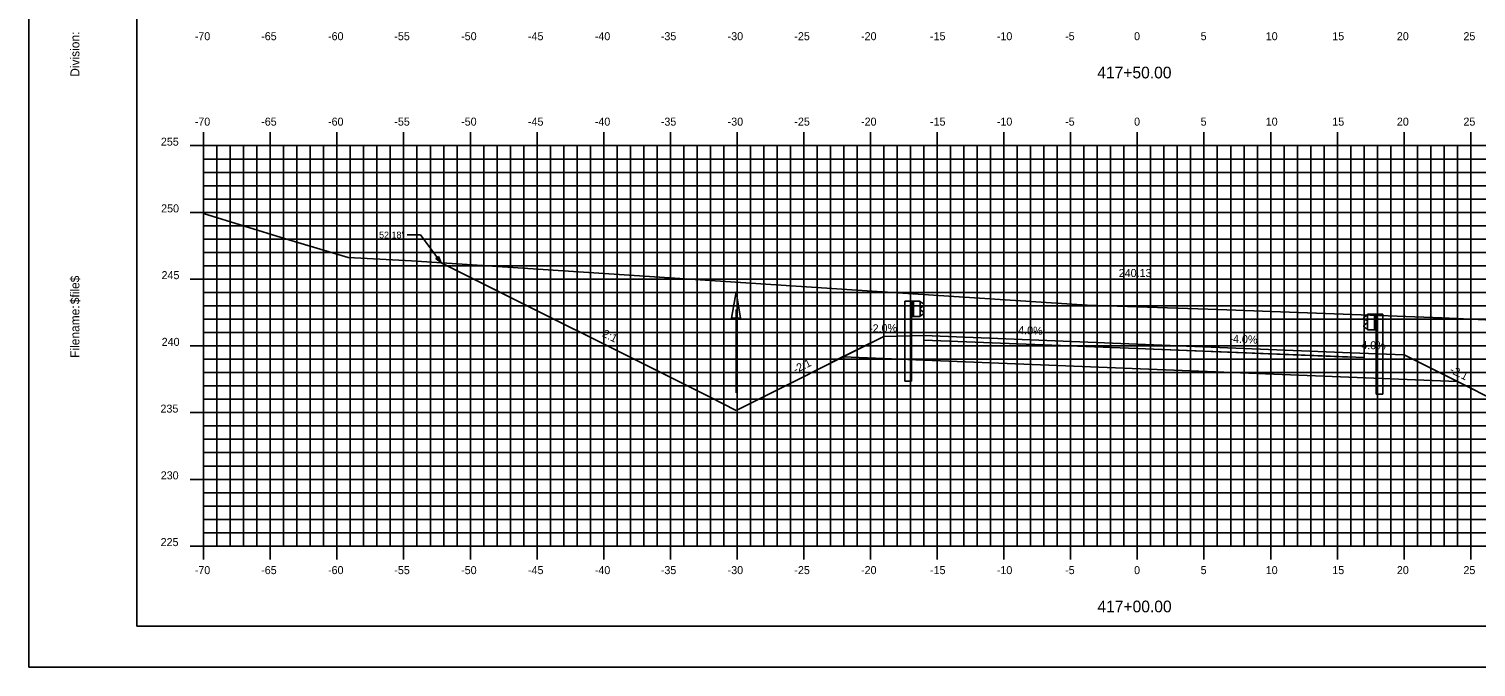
# Model space of a CAD drawing. Extents: x 1160718 to 1173142, y 616002 to 617630.
# Drawn here: x 1168770.5 to 1168879, y 616613.9 to 616661.7 of the extents above; entities that cross this region are included whole.
import ezdxf

# ---------------------------------------------------------------- set-up
doc = ezdxf.new("R2010")
doc.units = 0
for name, color, linetype in [('ANNOTATION', 7, 'Continuous'), ('BORDER', 7, 'Continuous'), ('D_Drainage_Ditch_Line', 7, 'Continuous'), ('D_Guardrail_Beam_Lt', 7, 'Continuous'), ('D_Guardrail_Beam_Rt', 7, 'Continuous'), ('D_Roadway_Centerline', 7, 'Continuous'), ('D_Roadway_Centerline_Text', 7, 'Continuous'), ('D_Roadway_Edge_Shoulder', 7, 'Continuous'), ('D_Roadway_Edge_TW', 7, 'Continuous'), ('D_Roadway_Pavement', 7, 'Continuous'), ('D_Roadway_SlopeLines', 7, 'Continuous'), ('D_Roadway_SubGrade', 7, 'Continuous'), ('H_V ANNOTATION', 7, 'Continuous'), ('MAJOR', 7, 'Continuous'), ('MINOR', 7, 'Continuous'), ('PLOT BOUNDARY', 7, 'Continuous'), ('S_Roadway_Centerline', 7, 'Continuous'), ('SHADING', 7, 'Continuous')]:
    doc.layers.add(name, color=color, linetype=linetype)

msp = doc.modelspace()

# ---------------------------------------------------------------- linework, layer by layer
at = {"layer": 'ANNOTATION'}
for p, q in [((1168798.87, 616646.24), (1168799.87, 616646.24)), ((1168801.43, 616644.15), (1168799.87, 616646.24)), ((1168869.61, 616637.42), (1168873.61, 616637.26))]:
    msp.add_line(p, q, dxfattribs=at)
msp.add_lwpolyline([(1168801.23, 616644.62), (1168801.43, 616644.15), (1168801.03, 616644.47)], close=True, dxfattribs=at)
at = {"layer": 'BORDER'}
for p, q in [((1168778.61, 616721.93), (1168778.61, 616616.93)), ((1168778.61, 616616.93), (1168938.61, 616616.93))]:
    msp.add_line(p, q, dxfattribs=at)
at = {"layer": 'D_Drainage_Ditch_Line'}
msp.add_line((1168823.53, 616640.65), (1168823.53, 616634.41), dxfattribs=at)
msp.add_lwpolyline([(1168823.86, 616640), (1168823.2, 616640), (1168823.53, 616641.97)], close=True, dxfattribs=at)
at = {"layer": 'D_Guardrail_Beam_Lt'}
for p, q in [((1168836.18, 616641.28), (1168836.18, 616635.28)), ((1168836.65, 616641.28), (1168836.18, 616641.28)), ((1168837.34, 616641.28), (1168836.65, 616641.28)), ((1168836.65, 616641.28), (1168836.65, 616640.12)), ((1168836.72, 616641.28), (1168836.72, 616640.12)), ((1168836.82, 616641.28), (1168836.82, 616640.12)), ((1168837.34, 616640.12), (1168837.34, 616641.28)), ((1168837.34, 616641.2), (1168837.41, 616641.19)), ((1168837.43, 616641.18), (1168837.57, 616641.08)), ((1168836.65, 616640.12), (1168837.34, 616640.12)), ((1168836.67, 616635.28), (1168836.67, 616640.12)), ((1168837.34, 616640.73), (1168837.34, 616640.66)), ((1168837.41, 616640.21), (1168837.34, 616640.2)), ((1168837.57, 616640.94), (1168837.38, 616640.8)), ((1168837.38, 616640.6), (1168837.57, 616640.46)), ((1168837.57, 616640.32), (1168837.43, 616640.22)), ((1168836.67, 616635.28), (1168836.18, 616635.28))]:
    msp.add_line(p, q, dxfattribs=at)
for centre, major_axis, start_param, end_param in [((1168837.41, 616641.14), (0.0417, 0), 0.959931, 1.376053), ((1168837.52, 616641.01), (0.0877, 0), 5.323254, 7.243116), ((1168837.42, 616640.73), (-0.0789, 0), 5.323254, 6.283185), ((1168837.42, 616640.66), (-0.0789, 0), 6.283185, 7.243116), ((1168837.41, 616640.25), (0.0417, 0), 4.907132, 5.323254), ((1168837.52, 616640.39), (0.0877, 0), 5.323254, 7.243116)]:
    msp.add_ellipse(centre, major_axis=major_axis, ratio=0.995501, start_param=start_param, end_param=end_param, dxfattribs=at)
at = {"layer": 'D_Guardrail_Beam_Rt'}
for p, q in [((1168870.77, 616640.19), (1168870.63, 616640.09)), ((1168870.63, 616639.95), (1168870.83, 616639.82)), ((1168870.86, 616640.22), (1168870.79, 616640.2)), ((1168870.86, 616640.3), (1168871.55, 616640.3)), ((1168870.86, 616639.13), (1168870.86, 616640.3)), ((1168871.39, 616640.3), (1168871.39, 616639.13)), ((1168871.49, 616640.3), (1168871.49, 616639.13)), ((1168871.55, 616640.3), (1168872.02, 616640.3)), ((1168871.55, 616640.3), (1168871.55, 616639.13)), ((1168872.02, 616640.3), (1168872.02, 616634.3)), ((1168870.83, 616639.62), (1168870.63, 616639.48)), ((1168870.63, 616639.34), (1168870.77, 616639.24)), ((1168870.79, 616639.23), (1168870.86, 616639.22)), ((1168870.86, 616639.75), (1168870.86, 616639.68)), ((1168871.55, 616639.13), (1168870.86, 616639.13)), ((1168871.53, 616634.3), (1168871.53, 616639.13)), ((1168871.53, 616634.3), (1168872.02, 616634.3))]:
    msp.add_line(p, q, dxfattribs=at)
for centre, major_axis, start_param, end_param in [((1168870.68, 616640.02), (-0.0877, 0), 5.323254, 7.243116), ((1168870.8, 616640.16), (-0.0417, 0), 4.907132, 5.323254), ((1168870.68, 616639.41), (-0.0877, 0), 5.323254, 7.243116), ((1168870.8, 616639.27), (-0.0417, 0), 0.959931, 1.376053), ((1168870.78, 616639.75), (0.0789, 0), 0, 0.959931), ((1168870.78, 616639.68), (0.0789, 0), 5.323254, 6.283185)]:
    msp.add_ellipse(centre, major_axis=major_axis, ratio=0.995501, start_param=start_param, end_param=end_param, dxfattribs=at)
at = {"layer": 'D_Roadway_Edge_Shoulder'}
msp.add_lwpolyline([(1168837.61, 616638.7), (1168837.61, 616638.37)], dxfattribs=at)
at = {"layer": 'D_Roadway_Edge_TW'}
for p, q in [((1168837.61, 616638.37), (1168837.61, 616638.7)), ((1168837.61, 616638.7), (1168853.61, 616638.06)), ((1168853.61, 616637.73), (1168837.61, 616638.37)), ((1168853.61, 616638.06), (1168869.61, 616637.42)), ((1168870.61, 616637.05), (1168853.61, 616637.73))]:
    msp.add_line(p, q, dxfattribs=at)
at = {"layer": 'D_Roadway_Pavement'}
msp.add_lwpolyline([(1168837.61, 616638.37), (1168837.61, 616638.37), (1168853.61, 616637.73), (1168869.61, 616637.09), (1168869.61, 616637.09), (1168853.61, 616637.73)], close=True, dxfattribs=at)
for points in [[(1168837.61, 616638.37), (1168837.61, 616638.37)], [(1168837.61, 616638.37), (1168837.61, 616638.37)], [(1168869.61, 616637.09), (1168869.61, 616637.09)], [(1168869.61, 616637.09), (1168869.61, 616637.09)]]:
    msp.add_lwpolyline(points, dxfattribs=at)
at = {"layer": 'D_Roadway_SlopeLines'}
for points in [[(1168834.61, 616638.64), (1168823.53, 616633.1)], [(1168873.61, 616637.26), (1168884.69, 616631.72)]]:
    msp.add_lwpolyline(points, dxfattribs=at)
at = {"layer": 'D_Roadway_SubGrade'}
for p, q in [((1168834.61, 616638.64), (1168830.62, 616636.65)), ((1168837.61, 616638.7), (1168834.61, 616638.64)), ((1168837.61, 616636.87), (1168837.61, 616638.7)), ((1168837.61, 616636.87), (1168837.61, 616638.37)), ((1168837.61, 616638.37), (1168853.61, 616637.73)), ((1168853.61, 616637.73), (1168869.61, 616637.09)), ((1168870.61, 616635.55), (1168870.61, 616637.38))]:
    msp.add_line(p, q, dxfattribs=at)
msp.add_lwpolyline([(1168823.53, 616633.1), (1168821.53, 616634.1), (1168801.43, 616644.15)], dxfattribs=at)
at = {"layer": 'MAJOR'}
for p, q in [((1168783.61, 616653.93), (1168783.61, 616652.93)), ((1168788.61, 616653.93), (1168788.61, 616652.93)), ((1168793.61, 616653.93), (1168793.61, 616652.93)), ((1168798.61, 616653.93), (1168798.61, 616652.93)), ((1168803.61, 616653.93), (1168803.61, 616652.93)), ((1168808.61, 616653.93), (1168808.61, 616652.93)), ((1168813.61, 616653.93), (1168813.61, 616652.93)), ((1168818.61, 616653.93), (1168818.61, 616652.93)), ((1168823.61, 616653.93), (1168823.61, 616652.93)), ((1168828.61, 616653.93), (1168828.61, 616652.93)), ((1168833.61, 616653.93), (1168833.61, 616652.93)), ((1168838.61, 616653.93), (1168838.61, 616652.93)), ((1168843.61, 616653.93), (1168843.61, 616652.93)), ((1168848.61, 616653.93), (1168848.61, 616652.93)), ((1168853.61, 616653.93), (1168853.61, 616652.93)), ((1168858.61, 616653.93), (1168858.61, 616652.93)), ((1168863.61, 616653.93), (1168863.61, 616652.93)), ((1168868.61, 616653.93), (1168868.61, 616652.93)), ((1168873.61, 616653.93), (1168873.61, 616652.93)), ((1168878.61, 616653.93), (1168878.61, 616652.93)), ((1168782.61, 616652.93), (1168783.61, 616652.93)), ((1168783.61, 616652.93), (1168923.61, 616652.93)), ((1168783.61, 616622.93), (1168783.61, 616652.93)), ((1168783.61, 616622.93), (1168783.61, 616652.93)), ((1168783.61, 616652.93), (1168923.61, 616652.93)), ((1168788.61, 616622.93), (1168788.61, 616652.93)), ((1168793.61, 616622.93), (1168793.61, 616652.93)), ((1168798.61, 616622.93), (1168798.61, 616652.93)), ((1168803.61, 616622.93), (1168803.61, 616652.93)), ((1168808.61, 616622.93), (1168808.61, 616652.93)), ((1168813.61, 616622.93), (1168813.61, 616652.93)), ((1168818.61, 616622.93), (1168818.61, 616652.93)), ((1168823.61, 616622.93), (1168823.61, 616652.93)), ((1168828.61, 616622.93), (1168828.61, 616652.93)), ((1168833.61, 616622.93), (1168833.61, 616652.93)), ((1168838.61, 616622.93), (1168838.61, 616652.93)), ((1168843.61, 616622.93), (1168843.61, 616652.93)), ((1168848.61, 616622.93), (1168848.61, 616652.93)), ((1168853.61, 616622.93), (1168853.61, 616652.93)), ((1168858.61, 616622.93), (1168858.61, 616652.93)), ((1168863.61, 616622.93), (1168863.61, 616652.93)), ((1168868.61, 616622.93), (1168868.61, 616652.93)), ((1168873.61, 616622.93), (1168873.61, 616652.93)), ((1168878.61, 616622.93), (1168878.61, 616652.93)), ((1168782.61, 616647.93), (1168783.61, 616647.93)), ((1168783.61, 616647.93), (1168923.61, 616647.93)), ((1168782.61, 616642.93), (1168783.61, 616642.93)), ((1168783.61, 616642.93), (1168923.61, 616642.93)), ((1168782.61, 616637.93), (1168783.61, 616637.93)), ((1168783.61, 616637.93), (1168923.61, 616637.93)), ((1168782.61, 616632.93), (1168783.61, 616632.93)), ((1168783.61, 616632.93), (1168923.61, 616632.93)), ((1168782.61, 616627.93), (1168783.61, 616627.93)), ((1168783.61, 616627.93), (1168923.61, 616627.93)), ((1168782.61, 616622.93), (1168783.61, 616622.93)), ((1168783.61, 616622.93), (1168923.61, 616622.93)), ((1168783.61, 616622.93), (1168923.61, 616622.93)), ((1168783.61, 616621.93), (1168783.61, 616622.93)), ((1168788.61, 616621.93), (1168788.61, 616622.93)), ((1168793.61, 616621.93), (1168793.61, 616622.93)), ((1168798.61, 616621.93), (1168798.61, 616622.93)), ((1168803.61, 616621.93), (1168803.61, 616622.93)), ((1168808.61, 616621.93), (1168808.61, 616622.93)), ((1168813.61, 616621.93), (1168813.61, 616622.93)), ((1168818.61, 616621.93), (1168818.61, 616622.93)), ((1168823.61, 616621.93), (1168823.61, 616622.93)), ((1168828.61, 616621.93), (1168828.61, 616622.93)), ((1168833.61, 616621.93), (1168833.61, 616622.93)), ((1168838.61, 616621.93), (1168838.61, 616622.93)), ((1168843.61, 616621.93), (1168843.61, 616622.93)), ((1168848.61, 616621.93), (1168848.61, 616622.93)), ((1168853.61, 616621.93), (1168853.61, 616622.93)), ((1168858.61, 616621.93), (1168858.61, 616622.93)), ((1168863.61, 616621.93), (1168863.61, 616622.93)), ((1168868.61, 616621.93), (1168868.61, 616622.93)), ((1168873.61, 616621.93), (1168873.61, 616622.93)), ((1168878.61, 616621.93), (1168878.61, 616622.93))]:
    msp.add_line(p, q, dxfattribs=at)
at = {"layer": 'MINOR'}
for p, q in [((1168783.61, 616651.93), (1168923.61, 616651.93)), ((1168783.61, 616651.93), (1168784.61, 616651.93)), ((1168784.61, 616622.93), (1168784.61, 616652.93)), ((1168785.61, 616622.93), (1168785.61, 616652.93)), ((1168786.61, 616622.93), (1168786.61, 616652.93)), ((1168787.61, 616622.93), (1168787.61, 616652.93)), ((1168789.61, 616622.93), (1168789.61, 616652.93)), ((1168790.61, 616622.93), (1168790.61, 616652.93)), ((1168791.61, 616622.93), (1168791.61, 616652.93)), ((1168792.61, 616622.93), (1168792.61, 616652.93)), ((1168794.61, 616622.93), (1168794.61, 616652.93)), ((1168795.61, 616622.93), (1168795.61, 616652.93)), ((1168796.61, 616622.93), (1168796.61, 616652.93)), ((1168797.61, 616622.93), (1168797.61, 616652.93)), ((1168799.61, 616622.93), (1168799.61, 616652.93)), ((1168800.61, 616622.93), (1168800.61, 616652.93)), ((1168801.61, 616622.93), (1168801.61, 616652.93)), ((1168802.61, 616622.93), (1168802.61, 616652.93)), ((1168804.61, 616622.93), (1168804.61, 616652.93)), ((1168805.61, 616622.93), (1168805.61, 616652.93)), ((1168806.61, 616622.93), (1168806.61, 616652.93)), ((1168807.61, 616622.93), (1168807.61, 616652.93)), ((1168809.61, 616622.93), (1168809.61, 616652.93)), ((1168810.61, 616622.93), (1168810.61, 616652.93)), ((1168811.61, 616622.93), (1168811.61, 616652.93)), ((1168812.61, 616622.93), (1168812.61, 616652.93)), ((1168814.61, 616622.93), (1168814.61, 616652.93)), ((1168815.61, 616622.93), (1168815.61, 616652.93)), ((1168816.61, 616622.93), (1168816.61, 616652.93)), ((1168817.61, 616622.93), (1168817.61, 616652.93)), ((1168819.61, 616622.93), (1168819.61, 616652.93)), ((1168820.61, 616622.93), (1168820.61, 616652.93)), ((1168821.61, 616622.93), (1168821.61, 616652.93)), ((1168822.61, 616622.93), (1168822.61, 616652.93)), ((1168824.61, 616622.93), (1168824.61, 616652.93)), ((1168825.61, 616622.93), (1168825.61, 616652.93)), ((1168826.61, 616622.93), (1168826.61, 616652.93)), ((1168827.61, 616622.93), (1168827.61, 616652.93)), ((1168829.61, 616622.93), (1168829.61, 616652.93)), ((1168830.61, 616622.93), (1168830.61, 616652.93)), ((1168831.61, 616622.93), (1168831.61, 616652.93)), ((1168832.61, 616622.93), (1168832.61, 616652.93)), ((1168834.61, 616622.93), (1168834.61, 616652.93)), ((1168835.61, 616622.93), (1168835.61, 616652.93)), ((1168836.61, 616622.93), (1168836.61, 616652.93)), ((1168837.61, 616622.93), (1168837.61, 616652.93)), ((1168839.61, 616622.93), (1168839.61, 616652.93)), ((1168840.61, 616622.93), (1168840.61, 616652.93)), ((1168841.61, 616622.93), (1168841.61, 616652.93)), ((1168842.61, 616622.93), (1168842.61, 616652.93)), ((1168844.61, 616622.93), (1168844.61, 616652.93)), ((1168845.61, 616622.93), (1168845.61, 616652.93)), ((1168846.61, 616622.93), (1168846.61, 616652.93)), ((1168847.61, 616622.93), (1168847.61, 616652.93)), ((1168849.61, 616622.93), (1168849.61, 616652.93)), ((1168850.61, 616622.93), (1168850.61, 616652.93)), ((1168851.61, 616622.93), (1168851.61, 616652.93)), ((1168852.61, 616622.93), (1168852.61, 616652.93)), ((1168854.61, 616622.93), (1168854.61, 616652.93)), ((1168855.61, 616622.93), (1168855.61, 616652.93)), ((1168856.61, 616622.93), (1168856.61, 616652.93)), ((1168857.61, 616622.93), (1168857.61, 616652.93)), ((1168859.61, 616622.93), (1168859.61, 616652.93)), ((1168860.61, 616622.93), (1168860.61, 616652.93)), ((1168861.61, 616622.93), (1168861.61, 616652.93)), ((1168862.61, 616622.93), (1168862.61, 616652.93)), ((1168864.61, 616622.93), (1168864.61, 616652.93)), ((1168865.61, 616622.93), (1168865.61, 616652.93)), ((1168866.61, 616622.93), (1168866.61, 616652.93)), ((1168867.61, 616622.93), (1168867.61, 616652.93)), ((1168869.61, 616622.93), (1168869.61, 616652.93)), ((1168870.61, 616622.93), (1168870.61, 616652.93)), ((1168871.61, 616622.93), (1168871.61, 616652.93)), ((1168872.61, 616622.93), (1168872.61, 616652.93)), ((1168874.61, 616622.93), (1168874.61, 616652.93)), ((1168875.61, 616622.93), (1168875.61, 616652.93)), ((1168876.61, 616622.93), (1168876.61, 616652.93)), ((1168877.61, 616622.93), (1168877.61, 616652.93)), ((1168783.61, 616650.93), (1168923.61, 616650.93)), ((1168783.61, 616650.93), (1168784.61, 616650.93)), ((1168783.61, 616649.93), (1168923.61, 616649.93)), ((1168783.61, 616649.93), (1168784.61, 616649.93)), ((1168783.61, 616648.93), (1168923.61, 616648.93)), ((1168783.61, 616648.93), (1168784.61, 616648.93)), ((1168783.61, 616646.93), (1168923.61, 616646.93)), ((1168783.61, 616646.93), (1168784.61, 616646.93)), ((1168783.61, 616645.93), (1168923.61, 616645.93)), ((1168783.61, 616645.93), (1168784.61, 616645.93)), ((1168783.61, 616644.93), (1168923.61, 616644.93)), ((1168783.61, 616644.93), (1168784.61, 616644.93)), ((1168783.61, 616643.93), (1168923.61, 616643.93)), ((1168783.61, 616643.93), (1168784.61, 616643.93)), ((1168783.61, 616641.93), (1168923.61, 616641.93)), ((1168783.61, 616641.93), (1168784.61, 616641.93)), ((1168783.61, 616640.93), (1168923.61, 616640.93)), ((1168783.61, 616640.93), (1168784.61, 616640.93)), ((1168783.61, 616639.93), (1168923.61, 616639.93)), ((1168783.61, 616639.93), (1168784.61, 616639.93)), ((1168783.61, 616638.93), (1168923.61, 616638.93)), ((1168783.61, 616638.93), (1168784.61, 616638.93)), ((1168783.61, 616636.93), (1168923.61, 616636.93)), ((1168783.61, 616636.93), (1168784.61, 616636.93)), ((1168783.61, 616635.93), (1168923.61, 616635.93)), ((1168783.61, 616635.93), (1168784.61, 616635.93)), ((1168783.61, 616634.93), (1168923.61, 616634.93)), ((1168783.61, 616634.93), (1168784.61, 616634.93)), ((1168783.61, 616633.93), (1168923.61, 616633.93)), ((1168783.61, 616633.93), (1168784.61, 616633.93)), ((1168783.61, 616631.93), (1168923.61, 616631.93)), ((1168783.61, 616631.93), (1168784.61, 616631.93)), ((1168783.61, 616630.93), (1168923.61, 616630.93)), ((1168783.61, 616630.93), (1168784.61, 616630.93)), ((1168783.61, 616629.93), (1168923.61, 616629.93)), ((1168783.61, 616629.93), (1168784.61, 616629.93)), ((1168783.61, 616628.93), (1168923.61, 616628.93)), ((1168783.61, 616628.93), (1168784.61, 616628.93)), ((1168783.61, 616626.93), (1168923.61, 616626.93)), ((1168783.61, 616626.93), (1168784.61, 616626.93)), ((1168783.61, 616625.93), (1168923.61, 616625.93)), ((1168783.61, 616625.93), (1168784.61, 616625.93)), ((1168783.61, 616624.93), (1168923.61, 616624.93)), ((1168783.61, 616624.93), (1168784.61, 616624.93)), ((1168783.61, 616623.93), (1168923.61, 616623.93)), ((1168783.61, 616623.93), (1168784.61, 616623.93))]:
    msp.add_line(p, q, dxfattribs=at)
at = {"layer": 'PLOT BOUNDARY'}
msp.add_lwpolyline([(1168770.52, 616613.87), (1168940.52, 616613.87), (1168940.52, 616723.87), (1168770.52, 616723.87)], close=True, dxfattribs=at)
at = {"layer": 'S_Roadway_Centerline'}
msp.add_lwpolyline([(1168783.61, 616647.84), (1168789.75, 616645.95), (1168794.45, 616644.54), (1168799.19, 616644.29), (1168835.26, 616641.92), (1168849.84, 616640.99), (1168859.64, 616640.66), (1168876.45, 616640.03), (1168887.85, 616639.5), (1168899.84, 616639.08), (1168906.03, 616638.98), (1168915.28, 616638.02), (1168917.51, 616637.54), (1168923.61, 616639.64)], dxfattribs=at)
at = {"layer": 'SHADING'}
msp.add_lwpolyline([(1168831.55, 616637.11), (1168837.61, 616636.87), (1168877.6, 616635.27)], dxfattribs=at)

# ---------------------------------------------------------------- texts
at = {"layer": 'ANNOTATION'}
msp.add_text("52.18'", height=0.5, dxfattribs=at).set_placement((1168796.77, 616645.99))
for s, rotation, p in [('2:1', 333.4349, (1168813.45, 616638.66)), ('-2.0%', 1.1458, (1168833.51, 616638.94)), ('4.0%', 357.7094, (1168844.67, 616638.82)), ('-4.0%', 357.7094, (1168860.51, 616638.18)), ('-4.0%', 358.8542, (1168870.13, 616637.7)), ('-2:1', 26.5651, (1168828, 616635.85)), ('-2:1', 333.4349, (1168876.98, 616635.95))]:
    msp.add_text(s, height=0.6, rotation=rotation, dxfattribs=at).set_placement(p)
at = {"layer": 'BORDER'}
for s, p in [('Division:', (1168774.3, 616658.09)), ('$file$', (1168774.3, 616641.05)), ('Filename:', (1168774.3, 616637.03))]:
    msp.add_text(s, height=0.67, rotation=90, dxfattribs=at).set_placement(p)
at = {"layer": 'D_Roadway_Centerline'}
for s, p in [('C', (1168853.61, 616638.06)), ('L', (1168853.61, 616638.05))]:
    msp.add_text(s, height=0.0146, dxfattribs=at).set_placement(p)
at = {"layer": 'D_Roadway_Centerline_Text'}
msp.add_text('240.13', height=0.6, dxfattribs=at).set_placement((1168852.22, 616643.09))
at = {"layer": 'H_V ANNOTATION'}
for s, height, p in [('-70', 0.6, (1168782.95, 616660.83)), ('-65', 0.6, (1168787.93, 616660.83)), ('-60', 0.6, (1168792.94, 616660.83)), ('-55', 0.6, (1168797.91, 616660.83)), ('-50', 0.6, (1168802.92, 616660.83)), ('-45', 0.6, (1168807.93, 616660.83)), ('-40', 0.6, (1168812.94, 616660.83)), ('-35', 0.6, (1168817.89, 616660.83)), ('-30', 0.6, (1168822.9, 616660.83)), ('-25', 0.6, (1168827.9, 616660.83)), ('-20', 0.6, (1168832.9, 616660.83)), ('-15', 0.6, (1168838.07, 616660.83)), ('-10', 0.6, (1168843.08, 616660.83)), ('-5', 0.6, (1168848.2, 616660.83)), ('0', 0.6, (1168853.37, 616660.83)), ('5', 0.6, (1168858.36, 616660.83)), ('10', 0.6, (1168863.24, 616660.83)), ('15', 0.6, (1168868.23, 616660.83)), ('20', 0.6, (1168873.07, 616660.83)), ('25', 0.6, (1168878.06, 616660.83)), ('417+50.00', 0.875, (1168850.61, 616657.97)), ('-70', 0.6, (1168782.95, 616654.43)), ('-65', 0.6, (1168787.93, 616654.43)), ('-60', 0.6, (1168792.94, 616654.43)), ('-55', 0.6, (1168797.91, 616654.43)), ('-50', 0.6, (1168802.92, 616654.43)), ('-45', 0.6, (1168807.93, 616654.43)), ('-40', 0.6, (1168812.94, 616654.43)), ('-35', 0.6, (1168817.89, 616654.43)), ('-30', 0.6, (1168822.9, 616654.43)), ('-25', 0.6, (1168827.9, 616654.43)), ('-20', 0.6, (1168832.9, 616654.43)), ('-15', 0.6, (1168838.07, 616654.43)), ('-10', 0.6, (1168843.08, 616654.43)), ('-5', 0.6, (1168848.2, 616654.43)), ('0', 0.6, (1168853.37, 616654.43)), ('5', 0.6, (1168858.36, 616654.43)), ('10', 0.6, (1168863.24, 616654.43)), ('15', 0.6, (1168868.23, 616654.43)), ('20', 0.6, (1168873.07, 616654.43)), ('25', 0.6, (1168878.06, 616654.43)), ('255', 0.6, (1168780.41, 616652.93)), ('250', 0.6, (1168780.43, 616647.93)), ('245', 0.6, (1168780.46, 616642.93)), ('240', 0.6, (1168780.47, 616637.93)), ('235', 0.6, (1168780.38, 616632.93)), ('230', 0.6, (1168780.4, 616627.93)), ('225', 0.6, (1168780.39, 616622.93)), ('-70', 0.6, (1168782.95, 616620.83)), ('-65', 0.6, (1168787.93, 616620.83)), ('-60', 0.6, (1168792.94, 616620.83)), ('-55', 0.6, (1168797.91, 616620.83)), ('-50', 0.6, (1168802.92, 616620.83)), ('-45', 0.6, (1168807.93, 616620.83)), ('-40', 0.6, (1168812.94, 616620.83)), ('-35', 0.6, (1168817.89, 616620.83)), ('-30', 0.6, (1168822.9, 616620.83)), ('-25', 0.6, (1168827.9, 616620.83)), ('-20', 0.6, (1168832.9, 616620.83)), ('-15', 0.6, (1168838.07, 616620.83)), ('-10', 0.6, (1168843.08, 616620.83)), ('-5', 0.6, (1168848.2, 616620.83)), ('0', 0.6, (1168853.37, 616620.83)), ('5', 0.6, (1168858.36, 616620.83)), ('10', 0.6, (1168863.24, 616620.83)), ('15', 0.6, (1168868.23, 616620.83)), ('20', 0.6, (1168873.07, 616620.83)), ('25', 0.6, (1168878.06, 616620.83)), ('417+00.00', 0.875, (1168850.62, 616617.97))]:
    msp.add_text(s, height=height, dxfattribs=at).set_placement(p)

doc.saveas('drawing.dxf')
